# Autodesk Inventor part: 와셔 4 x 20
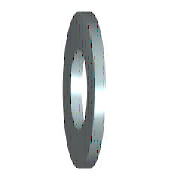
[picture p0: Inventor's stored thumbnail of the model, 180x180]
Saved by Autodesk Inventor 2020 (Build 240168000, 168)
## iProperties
IsCustomPart: 1
Created: 2012-02
Part Number: 와셔 4 x 20
Material: 강철, 연강
Description: 미터법 평면 와셔
Document SubType Name: Modeling
Standard: ANSI B18.22M
Designer: mduedu
Standard Revision: 1999
Standards Organization: ANSI
Language: ko-KR
Size Designation: 4 W
Categories: <MemberInstance><Categories><Category DisplayName="조임쇠" InternalName="e4da775c-781d-43d5-af7c-5136215cf5a6" Mnemonic="FSTN"><Category DisplayName="와셔" InternalN
Density: 1 g/cm^3
Appearance: 파란색 - 벽 페인트 - 광택
Author: mduedu
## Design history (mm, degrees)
sketch "스케치"
  geometry: C1 r 10 at (0, 0); C2 r 2.35 at (0, 0); 1 further point
  constraints: 2 centre point, 2 coincident
  dimensions: "d0" = 4.7 diameter of C2 (= SD1); "d1" = 20 diameter of C1 (= SD2)
extrude "본체" new body sketch "스케치" distance "d2" = 2.3 (= SD); taper "d3" = 0 deg
workaxis "Work Axis1"
workplane "Work Plane1"
body "Solid1"
other parameters: "SD1" = 4.7 [user parameter; used in 1 equation term], "SD2" = 20 [user parameter; used in 1 equation term], "SD" = 2.3 [user parameter; used in 1 equation term], "d4" = 0, "d5" = 0, "d6" = 0, "d7" = 0, "NND" = 4 [user parameter]
